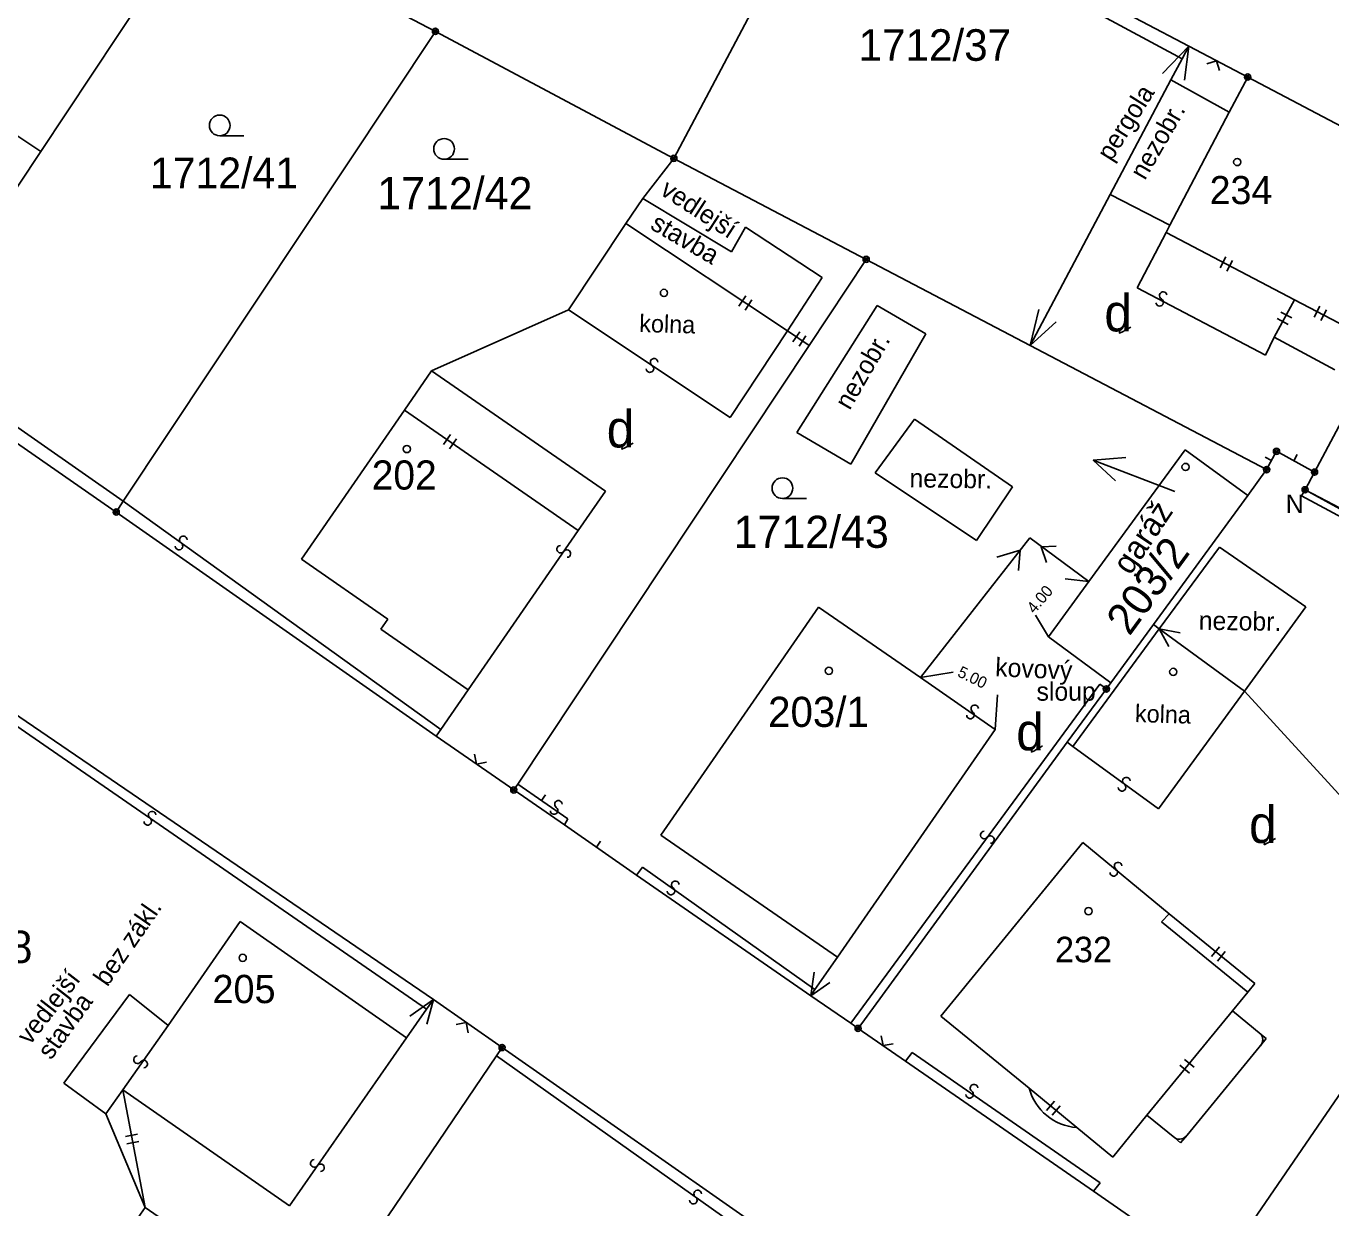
# Model space of a CAD drawing. Extents: x -815878 to -812162, y -1076286 to -1072327.
# Drawn here: x -813147.2 to -813083.7, y -1074584.2 to -1074526.7 of the extents above; entities that cross this region are included whole.
import ezdxf

# ---------------------------------------------------------------- set-up
doc = ezdxf.new("R2010")
doc.units = 0
for name, color, linetype in [('Vrstva 1', 7, 'Continuous'), ('Vrstva 18', 7, 'Continuous'), ('Vrstva 19', 7, 'Continuous'), ('Vrstva 24', 7, 'Continuous'), ('Vrstva 25', 7, 'Continuous'), ('Vrstva 39', 7, 'Continuous'), ('Vrstva 4', 7, 'Continuous'), ('Vrstva 56', 7, 'Continuous'), ('Vrstva 58', 7, 'Continuous'), ('Vrstva 62', 7, 'Continuous'), ('Vrstva 63', 7, 'Continuous')]:
    doc.layers.add(name, color=color, linetype=linetype)

msp = doc.modelspace()

# ---------------------------------------------------------------- linework, layer by layer
at = {"layer": 'Vrstva 1'}
for p, q in [((-813090.63, -1074527.71), (-813107.95, -1074518.6)), ((-813108.18, -1074519.03), (-813115.67, -1074533.16)), ((-813138.61, -1074521.03), (-813146.45, -1074532.82)), ((-813131, -1074525.03), (-813127.26, -1074526.99)), ((-813142.44, -1074549.83), (-813127.26, -1074526.99)), ((-813127.26, -1074526.99), (-813115.67, -1074533.16)), ((-813091.92, -1074529.04), (-813090.63, -1074527.71)), ((-813090.63, -1074527.71), (-813090.96, -1074528.33)), ((-813090.63, -1074527.71), (-813090.85, -1074529.36)), ((-813090.63, -1074527.71), (-813087.77, -1074529.21)), ((-813090.96, -1074528.33), (-813091.5, -1074529.35)), ((-813091.5, -1074529.35), (-813094.46, -1074534.92)), ((-813078.65, -1074534.01), (-813087.77, -1074529.21)), ((-813151.89, -1074541.01), (-813146.45, -1074532.82)), ((-813117.17, -1074535.11), (-813115.67, -1074533.16)), ((-813115.67, -1074533.16), (-813106.32, -1074538.07)), ((-813118, -1074536.33), (-813117.17, -1074535.11)), ((-813094.46, -1074534.92), (-813098.35, -1074542.25)), ((-813120.79, -1074540.53), (-813118, -1074536.33)), ((-813106.32, -1074538.07), (-813109.09, -1074542.25)), ((-813106.32, -1074538.07), (-813098.35, -1074542.25)), ((-813127.45, -1074543.49), (-813120.79, -1074540.53)), ((-813097.93, -1074540.5), (-813098.35, -1074542.25)), ((-813110.14, -1074541.55), (-813109.09, -1074542.25)), ((-813098.35, -1074542.25), (-813097.09, -1074541.11)), ((-813123.26, -1074563.58), (-813109.09, -1074542.25)), ((-813098.35, -1074542.25), (-813086.85, -1074548.29)), ((-813081.26, -1074542.26), (-813084.52, -1074548.41)), ((-813142.78, -1074550.35), (-813153.27, -1074543.09)), ((-813128.77, -1074545.4), (-813127.45, -1074543.49)), ((-813133.78, -1074552.64), (-813128.77, -1074545.4)), ((-813090.81, -1074547.32), (-813095.49, -1074553.72)), ((-813087.77, -1074549.54), (-813090.81, -1074547.32)), ((-813086.85, -1074548.29), (-813086.37, -1074547.4)), ((-813086.37, -1074547.4), (-813084.52, -1074548.41)), ((-813086.85, -1074548.29), (-813087.77, -1074549.54)), ((-813084.52, -1074548.41), (-813084.98, -1074549.27)), ((-813084.98, -1074549.27), (-813077.74, -1074553.08)), ((-813142.44, -1074549.83), (-813142.78, -1074550.35)), ((-813087.77, -1074549.54), (-813092.35, -1074555.82)), ((-813142.78, -1074550.35), (-813127.23, -1074561.24)), ((-813098.37, -1074551.61), (-813103.68, -1074558.4)), ((-813095.49, -1074553.72), (-813098.37, -1074551.61)), ((-813099.97, -1074552.54), (-813098.83, -1074552.21)), ((-813098.83, -1074552.21), (-813098.92, -1074553.2)), ((-813097.81, -1074552.04), (-813097.09, -1074552.01)), ((-813097.56, -1074552.81), (-813097.81, -1074552.04)), ((-813129.58, -1074555.55), (-813133.78, -1074552.64)), ((-813095.49, -1074553.72), (-813097.46, -1074556.42)), ((-813116.3, -1074566.05), (-813108.63, -1074554.97)), ((-813103.68, -1074558.4), (-813108.63, -1074554.97)), ((-813129.92, -1074556.05), (-813129.58, -1074555.55)), ((-813125.67, -1074558.99), (-813129.92, -1074556.05)), ((-813092.35, -1074555.82), (-813094.42, -1074558.65)), ((-813092.08, -1074556.02), (-813092.35, -1074555.82)), ((-813087.92, -1074559.06), (-813092.08, -1074556.02)), ((-813091.05, -1074556.22), (-813092.08, -1074556.02)), ((-813092.08, -1074556.02), (-813091.61, -1074556.88)), ((-813094.42, -1074558.65), (-813097.46, -1074556.42)), ((-813094.42, -1074558.65), (-813094.64, -1074558.95)), ((-813127, -1074560.92), (-813125.67, -1074558.99)), ((-813094.64, -1074558.95), (-813096.54, -1074561.54)), ((-813087.92, -1074559.06), (-813080.62, -1074567.04)), ((-813147.83, -1074560.08), (-813127.36, -1074574.05)), ((-813127.23, -1074561.24), (-813127, -1074560.92)), ((-813123.45, -1074563.86), (-813127.23, -1074561.24)), ((-813096.54, -1074561.54), (-813106.71, -1074575.45)), ((-813123.26, -1074563.58), (-813123.45, -1074563.86)), ((-813123.45, -1074563.86), (-813120.99, -1074565.55)), ((-813120.99, -1074565.55), (-813117.48, -1074568)), ((-813107.71, -1074571.99), (-813116.3, -1074566.05)), ((-813117.48, -1074568), (-813109.01, -1074573.86)), ((-813136.76, -1074570.26), (-813140.25, -1074575.3)), ((-813128.66, -1074575.91), (-813136.76, -1074570.26)), ((-813108.81, -1074573.56), (-813107.71, -1074571.99)), ((-813108.85, -1074572.71), (-813109.01, -1074573.86)), ((-813109.01, -1074573.86), (-813108.08, -1074573.21)), ((-813142.13, -1074573.8), (-813145.33, -1074578.11)), ((-813140.25, -1074575.3), (-813142.13, -1074573.8)), ((-813128.51, -1074574.86), (-813127.36, -1074574.05)), ((-813127.36, -1074574.05), (-813127.69, -1074574.52)), ((-813127.36, -1074574.05), (-813127.68, -1074575.25)), ((-813124.02, -1074576.38), (-813127.36, -1074574.05)), ((-813109.01, -1074573.86), (-813108.81, -1074573.56)), ((-813109.01, -1074573.86), (-813107.07, -1074575.2)), ((-813127.69, -1074574.52), (-813128.66, -1074575.91)), ((-813107.07, -1074575.2), (-813106.71, -1074575.45)), ((-813104.4, -1074577.04), (-813106.71, -1074575.45)), ((-813124.3, -1074576.78), (-813124.02, -1074576.38)), ((-813105.55, -1074589.27), (-813124.02, -1074576.38)), ((-813133.17, -1074589.87), (-813124.3, -1074576.78)), ((-813095.26, -1074583.36), (-813104.4, -1074577.04)), ((-813145.33, -1074578.11), (-813143.29, -1074579.6)), ((-813141.38, -1074584.15), (-813142.46, -1074578.43)), ((-813089.08, -1074587.08), (-813082.98, -1074578.19)), ((-813143.29, -1074579.6), (-813141.38, -1074584.15)), ((-813089.35, -1074587.46), (-813095.26, -1074583.36)), ((-813141.38, -1074584.15), (-813144.16, -1074588.13))]:
    msp.add_line(p, q, dxfattribs=at)
for centre, start, end in [((-813087.499, -1074575.995), 307.37303, 32.18263), ((-813091.095, -1074580.372), 241.02396, 325.83356)]:
    msp.add_arc(centre, 0.46, start, end, dxfattribs=at)
at = {"layer": 'Vrstva 24'}
for centre, radius in [((-813127.26, -1074526.99), 0.15), ((-813127.26, -1074526.99), 0.075), ((-813087.77, -1074529.21), 0.15), ((-813087.77, -1074529.21), 0.075), ((-813115.67, -1074533.16), 0.15), ((-813115.67, -1074533.16), 0.075), ((-813106.32, -1074538.07), 0.15), ((-813106.32, -1074538.07), 0.075), ((-813086.37, -1074547.4), 0.15), ((-813086.37, -1074547.4), 0.075), ((-813086.85, -1074548.29), 0.15), ((-813086.85, -1074548.29), 0.075), ((-813084.52, -1074548.41), 0.15), ((-813084.52, -1074548.41), 0.075), ((-813084.98, -1074549.27), 0.15), ((-813084.98, -1074549.27), 0.075), ((-813142.78, -1074550.35), 0.15), ((-813142.78, -1074550.35), 0.075), ((-813094.64, -1074558.95), 0.15), ((-813094.64, -1074558.95), 0.075), ((-813123.45, -1074563.86), 0.15), ((-813123.45, -1074563.86), 0.075), ((-813106.71, -1074575.45), 0.15), ((-813106.71, -1074575.45), 0.075), ((-813124.02, -1074576.38), 0.15), ((-813124.02, -1074576.38), 0.075)]:
    msp.add_circle(centre, radius, dxfattribs=at)
at = {"layer": 'Vrstva 25'}
for p, q in [((-813136.578, -1074532.062), (-813137.75, -1074532.062)), ((-813125.667, -1074533.203), (-813126.84, -1074533.203)), ((-813109.218, -1074549.693), (-813110.39, -1074549.693))]:
    msp.add_line(p, q, dxfattribs=at)
for centre, radius in [((-813137.75, -1074531.56), 0.503), ((-813126.84, -1074532.7), 0.503), ((-813088.28, -1074533.34), 0.175), ((-813116.15, -1074539.7), 0.175), ((-813128.65, -1074547.29), 0.175), ((-813090.79, -1074548.16), 0.175), ((-813110.39, -1074549.19), 0.503), ((-813108.13, -1074558.07), 0.175), ((-813091.39, -1074558.12), 0.175), ((-813095.51, -1074569.75), 0.175), ((-813136.63, -1074572.02), 0.175)]:
    msp.add_circle(centre, radius, dxfattribs=at)
for points in [[(-813093.989, -1074541.571), (-813093.989, -1074541.588), (-813094.028, -1074541.696), (-813093.458, -1074541.359)], [(-813118.182, -1074547.213), (-813118.182, -1074547.23), (-813118.221, -1074547.338), (-813117.651, -1074547.001)], [(-813098.272, -1074561.933), (-813098.272, -1074561.95), (-813098.311, -1074562.058), (-813097.741, -1074561.721)], [(-813086.952, -1074566.433), (-813086.952, -1074566.45), (-813086.991, -1074566.558), (-813086.421, -1074566.221)]]:
    msp.add_open_spline(points, degree=2, dxfattribs=at)
at = {"layer": 'Vrstva 39'}
for p, q in [((-813088.67, -1074530.91), (-813091.5, -1074529.35)), ((-813091.55, -1074536.41), (-813094.46, -1074534.92)), ((-813105.79, -1074540.31), (-813109.69, -1074546.48)), ((-813103.42, -1074541.69), (-813105.79, -1074540.31)), ((-813107.07, -1074548.03), (-813103.42, -1074541.69)), ((-813103.97, -1074545.84), (-813105.88, -1074548.44)), ((-813099.21, -1074549.13), (-813103.97, -1074545.84)), ((-813109.69, -1074546.48), (-813107.07, -1074548.03)), ((-813105.88, -1074548.44), (-813100.96, -1074551.73)), ((-813100.96, -1074551.73), (-813099.21, -1074549.13)), ((-813089.14, -1074552.06), (-813092.08, -1074556.02)), ((-813084.95, -1074554.96), (-813089.14, -1074552.06)), ((-813087.92, -1074559.06), (-813084.95, -1074554.96)), ((-813092.08, -1074556.02), (-813096.27, -1074561.74)), ((-813087.92, -1074559.06), (-813087.92, -1074559.06))]:
    msp.add_line(p, q, dxfattribs=at)
at = {"layer": 'Vrstva 4'}
for p, q in [((-813090.96, -1074528.33), (-813108.18, -1074519.03)), ((-813087.77, -1074529.21), (-813088.67, -1074530.91)), ((-813088.67, -1074530.91), (-813091.55, -1074536.41)), ((-813146.45, -1074532.82), (-813148.24, -1074531.63)), ((-813117.17, -1074535.11), (-813112.87, -1074537.71)), ((-813110.14, -1074541.55), (-813118, -1074536.33)), ((-813112.87, -1074537.71), (-813112.18, -1074536.51)), ((-813112.18, -1074536.51), (-813108.46, -1074538.95)), ((-813091.55, -1074536.41), (-813091.74, -1074536.76)), ((-813160.93, -1074536.89), (-813142.44, -1074549.83)), ((-813091.74, -1074536.76), (-813093.15, -1074539.45)), ((-813091.74, -1074536.76), (-813085.5, -1074540.04)), ((-813108.46, -1074538.95), (-813110.14, -1074541.55)), ((-813086.91, -1074542.73), (-813093.15, -1074539.45)), ((-813085.5, -1074540.04), (-813086.48, -1074541.85)), ((-813082.61, -1074541.55), (-813085.5, -1074540.04)), ((-813112.93, -1074545.75), (-813120.79, -1074540.53)), ((-813112.93, -1074545.75), (-813110.14, -1074541.55)), ((-813086.48, -1074541.85), (-813086.91, -1074542.73)), ((-813086.48, -1074541.85), (-813083.54, -1074543.44)), ((-813127.45, -1074543.49), (-813119, -1074549.34)), ((-813128.77, -1074545.4), (-813120.32, -1074551.25)), ((-813120.32, -1074551.25), (-813119, -1074549.34)), ((-813085.16, -1074549.57), (-813084.98, -1074549.27)), ((-813069.09, -1074558), (-813084.98, -1074549.27)), ((-813142.44, -1074549.83), (-813127, -1074560.92)), ((-813069.19, -1074558.14), (-813085.16, -1074549.57)), ((-813125.67, -1074558.99), (-813120.32, -1074551.25)), ((-813107.07, -1074575.2), (-813094.96, -1074558.71)), ((-813100.05, -1074560.92), (-813103.68, -1074558.4)), ((-813094.96, -1074558.71), (-813094.64, -1074558.95)), ((-813092.1, -1074564.78), (-813087.92, -1074559.06)), ((-813127.69, -1074574.52), (-813148.09, -1074560.43)), ((-813107.71, -1074571.99), (-813100.05, -1074560.92)), ((-813096.54, -1074561.54), (-813096.27, -1074561.74)), ((-813096.27, -1074561.74), (-813092.1, -1074564.78)), ((-813123.26, -1074563.58), (-813120.82, -1074565.27)), ((-813120.82, -1074565.27), (-813120.99, -1074565.55)), ((-813102.69, -1074574.85), (-813095.78, -1074566.42)), ((-813091.59, -1074569.88), (-813095.78, -1074566.42)), ((-813117.48, -1074568), (-813117.2, -1074567.61)), ((-813117.2, -1074567.61), (-813108.81, -1074573.56)), ((-813091.59, -1074569.88), (-813091.96, -1074570.27)), ((-813091.96, -1074570.27), (-813087.77, -1074573.69)), ((-813087.42, -1074573.27), (-813091.59, -1074569.88)), ((-813087.77, -1074573.69), (-813087.42, -1074573.27)), ((-813088.51, -1074574.59), (-813087.77, -1074573.69)), ((-813092.67, -1074579.67), (-813088.51, -1074574.59)), ((-813087.11, -1074575.75), (-813088.51, -1074574.59)), ((-813140.25, -1074575.3), (-813142.46, -1074578.43)), ((-813098.4, -1074578.35), (-813102.69, -1074574.85)), ((-813128.66, -1074575.91), (-813134.36, -1074584.08)), ((-813087.22, -1074576.36), (-813086.88, -1074575.94)), ((-813086.88, -1074575.94), (-813087.11, -1074575.75)), ((-813104.4, -1074577.04), (-813104.08, -1074576.62)), ((-813104.08, -1074576.62), (-813094.95, -1074582.96)), ((-813090.715, -1074580.63), (-813087.22, -1074576.36)), ((-813105.93, -1074589.8), (-813124.3, -1074576.78)), ((-813143.29, -1074579.6), (-813142.46, -1074578.43)), ((-813142.46, -1074578.43), (-813134.36, -1074584.08)), ((-813096.08, -1074580.27), (-813098.4, -1074578.35)), ((-813094.33, -1074581.7), (-813092.67, -1074579.67)), ((-813091.318, -1074580.774), (-813092.67, -1074579.67)), ((-813094.33, -1074581.7), (-813096.08, -1074580.27)), ((-813091.03, -1074581.01), (-813091.318, -1074580.774)), ((-813091.03, -1074581.01), (-813090.715, -1074580.63)), ((-813094.95, -1074582.96), (-813095.26, -1074583.36)), ((-813138.61, -1074586.06), (-813141.38, -1074584.15))]:
    msp.add_line(p, q, dxfattribs=at)
msp.add_arc((-813095.869, -1074577.654), 2.625, 195.38149, 265.39713, dxfattribs=at)
at = {"layer": 'Vrstva 58'}
for p, q in [((-813096.65, -1074553.59), (-813095.49, -1074553.72)), ((-813097.46, -1074556.42), (-813098.09, -1074555.36)), ((-813103.68, -1074558.4), (-813102.09, -1074558.13)), ((-813099.93, -1074559.24), (-813100.05, -1074560.92))]:
    msp.add_line(p, q, dxfattribs=at)
at = {"layer": 'Vrstva 62'}
for p, q in [((-813089.757, -1074528.562), (-813089.286, -1074528.415)), ((-813089.286, -1074528.415), (-813089.14, -1074528.886)), ((-813089.108, -1074538.483), (-813088.829, -1074537.951)), ((-813088.789, -1074538.65), (-813088.51, -1074538.119)), ((-813112.176, -1074539.838), (-813112.508, -1074540.338)), ((-813111.876, -1074540.037), (-813112.208, -1074540.537)), ((-813084.259, -1074540.35), (-813084.537, -1074540.882)), ((-813086.332, -1074540.946), (-813085.804, -1074541.231)), ((-813086.16, -1074540.629), (-813085.632, -1074540.915)), ((-813083.94, -1074540.517), (-813084.218, -1074541.048)), ((-813109.879, -1074542.084), (-813109.546, -1074541.585)), ((-813109.58, -1074542.284), (-813109.247, -1074541.785)), ((-813126.876, -1074547.076), (-813126.535, -1074546.583)), ((-813126.58, -1074547.281), (-813126.239, -1074546.788)), ((-813086.921, -1074547.684), (-813086.613, -1074547.85)), ((-813085.359, -1074547.549), (-813085.526, -1074547.857)), ((-813125.268, -1074562.6), (-813125.355, -1074562.115)), ((-813124.782, -1074562.512), (-813125.268, -1074562.6)), ((-813121.912, -1074564.088), (-813122.111, -1074564.376)), ((-813119.23, -1074566.351), (-813119.431, -1074566.638)), ((-813089.146, -1074571.48), (-813089.524, -1074571.946)), ((-813088.867, -1074571.707), (-813089.245, -1074572.173)), ((-813125.759, -1074575.167), (-813126.249, -1074575.253)), ((-813125.67, -1074575.656), (-813125.759, -1074575.167)), ((-813105.5, -1074576.287), (-813105.587, -1074575.802)), ((-813105.015, -1074576.199), (-813105.5, -1074576.287)), ((-813090.602, -1074577.618), (-813091.066, -1074577.238)), ((-813090.374, -1074577.34), (-813090.838, -1074576.96)), ((-813097.168, -1074578.981), (-813097.55, -1074579.443)), ((-813096.89, -1074579.21), (-813097.273, -1074579.672)), ((-813141.747, -1074580.587), (-813142.337, -1074580.698)), ((-813141.681, -1074580.941), (-813142.27, -1074581.052))]:
    msp.add_line(p, q, dxfattribs=at)
for centre, start, end in [((-813091.877, -1074539.831), 9.65944, 241.75743), ((-813092.05, -1074540.156), 189.44498, 62.03498), ((-813116.627, -1074543.073), 3.78372, 235.88171), ((-813116.833, -1074543.379), 183.56926, 56.15926), ((-813139.732, -1074552.002), 181.6844, 53.78239), ((-813139.515, -1074551.704), 1.46994, 234.05994), ((-813121.17, -1074552.156), 92.50549, 325.09549), ((-813120.868, -1074552.367), 272.71994, 144.81794), ((-813101.249, -1074560.216), 182.87532, 54.97331), ((-813101.038, -1074559.914), 2.66086, 235.25086), ((-813093.669, -1074563.428), 2.66086, 235.25086), ((-813093.88, -1074563.73), 182.87532, 54.97331), ((-813121.28, -1074564.56), 2.52709, 235.11709), ((-813141.034, -1074565.08), 2.74043, 234.83843), ((-813121.491, -1074564.862), 182.74155, 54.83954), ((-813141.245, -1074565.381), 182.52597, 55.11597), ((-813100.577, -1074566.048), 90.8653, 323.4553), ((-813100.282, -1074566.268), 271.07975, 143.17775), ((-813094.28, -1074567.86), 182.87532, 54.97331), ((-813094.069, -1074567.558), 2.66086, 235.25086), ((-813115.602, -1074568.467), 2.52709, 235.11709), ((-813115.813, -1074568.769), 182.74155, 54.83954), ((-813141.75, -1074576.97), 92.51159, 324.60959), ((-813141.449, -1074577.183), 272.29713, 144.88713), ((-813101.291, -1074578.652), 182.87532, 54.97331), ((-813101.08, -1074578.35), 2.66086, 235.25086), ((-813133.15, -1074582.01), 92.51159, 324.60959), ((-813132.849, -1074582.223), 272.29713, 144.88713), ((-813114.507, -1074583.495), 2.04508, 234.14308), ((-813114.722, -1074583.794), 181.83063, 54.42063)]:
    msp.add_arc(centre, 0.184, start, end, dxfattribs=at)
at = {"layer": 'Vrstva 63'}
for p, q in [((-813095.29, -1074547.83), (-813093.7, -1074547.7)), ((-813091.31, -1074549.35), (-813095.29, -1074547.83)), ((-813095.29, -1074547.83), (-813095.29, -1074547.83)), ((-813095.29, -1074547.83), (-813094.19, -1074548.84))]:
    msp.add_line(p, q, dxfattribs=at)

# ---------------------------------------------------------------- texts
at = {"layer": 'Vrstva 18'}
for s, height, p in [('1712/37', 1.5341, (-813106.689, -1074528.419)), ('1712/41', 1.4895, (-813141.14, -1074534.61)), ('1712/42', 1.5608, (-813130.089, -1074535.631)), ('1712/43', 1.5599, (-813112.76, -1074552.091)), ('1712/48', 1.5686, (-813154.435, -1074572.27))]:
    msp.add_text(s, height=height, dxfattribs=at).set_placement(p)
at = {"layer": 'Vrstva 19'}
for s, height, p in [('234', 1.3646, (-813089.62, -1074535.385)), ('202', 1.4175, (-813130.36, -1074549.26)), ('203/1', 1.4644, (-813111.087, -1074560.795)), ('232', 1.2375, (-813097.134, -1074572.232)), ('205', 1.3738, (-813138.1, -1074574.22))]:
    msp.add_text(s, height=height, dxfattribs=at).set_placement(p)
msp.add_text('203/2', height=1.5179, rotation=53.91533, dxfattribs=at).set_placement((-813093.519, -1074556.417))
at = {"layer": 'Vrstva 25'}
for p in [(-813094.74, -1074541.57), (-813118.933, -1074547.212), (-813099.023, -1074561.932), (-813087.703, -1074566.432)]:
    msp.add_text('d', height=1.8, dxfattribs=at).set_placement(p)
at = {"layer": 'Vrstva 56'}
for s, height, rotation, p in [('pergola', 0.9, 57.87309, (-813094.402, -1074533.353)), ('nezobr.', 0.9, 60.01442, (-813092.768, -1074534.261)), ('vedlejší', 0.9, 327.0683, (-813116.392, -1074534.88)), ('stavba', 0.9, 329.69091, (-813116.871, -1074536.556)), ('kolna', 0.85, 358.42908, (-813117.359, -1074541.599)), ('nezobr.', 0.9, 60.01442, (-813107.12, -1074545.44)), ('nezobr.', 0.9, 359.13848, (-813104.216, -1074549.149)), ('garáž', 1.1362, 56.13501, (-813093.474, -1074553.466)), ('nezobr.', 0.9, 359.13848, (-813090.156, -1074556.069)), ('kovový', 0.9, 357.43068, (-813100.06, -1074558.33)), ('sloup', 0.9, 0.05275, (-813098.036, -1074559.521)), ('kolna', 0.85, 358.42908, (-813093.26, -1074560.56)), ('bez zákl.', 0.9, 55.40339, (-813143.211, -1074573.46)), ('vedlejší', 0.9, 52.14868, (-813146.978, -1074576.295)), ('stavba', 0.9, 54.19428, (-813145.95, -1074577.02))]:
    msp.add_text(s, height=height, rotation=rotation, dxfattribs=at).set_placement(p)
msp.add_text('N', height=0.9, dxfattribs=at).set_placement((-813085.92, -1074550.4))
at = {"layer": 'Vrstva 58'}
for s, rotation, p in [('4.00', 49.74478, (-813098.137, -1074555.323)), ('5.00', 333.83742, (-813101.923, -1074558.313))]:
    msp.add_text(s, height=0.5582, rotation=rotation, dxfattribs=at).set_placement(p)

doc.saveas('drawing.dxf')
